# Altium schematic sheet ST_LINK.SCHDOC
size A4; Revision: B.2
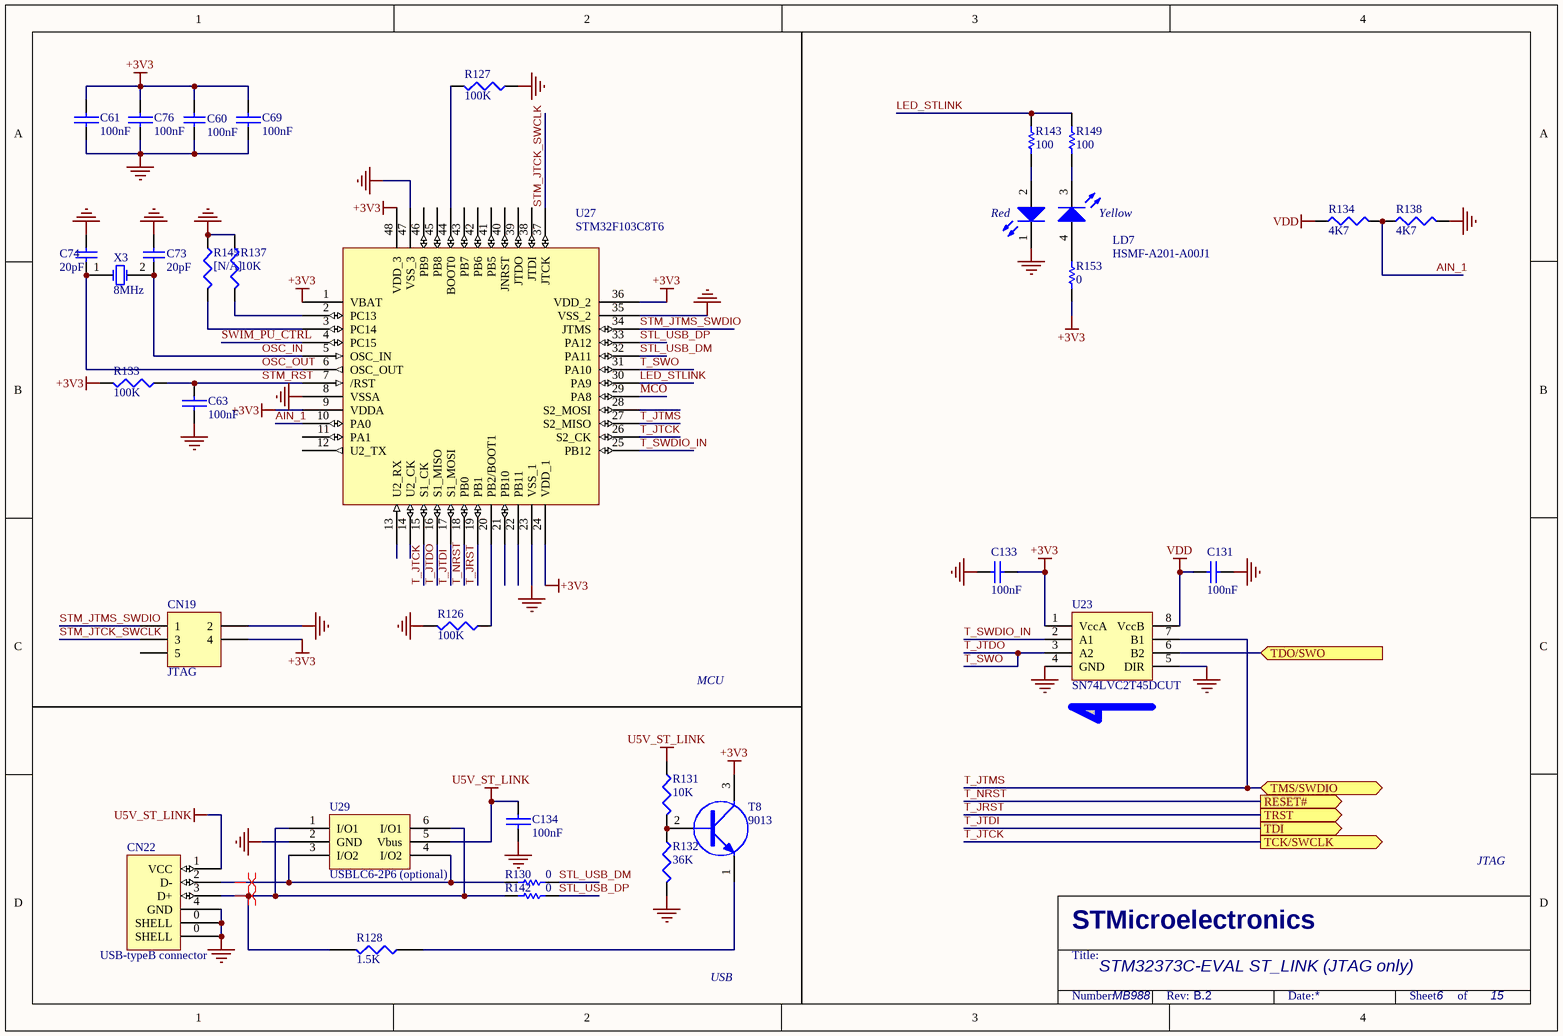
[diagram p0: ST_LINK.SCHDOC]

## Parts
C60  100nF  [0603C]
C61  100nF  [0603C]
C63  100nF  [0603C]
C69  100nF  [0603C]
C73  value 20pF  [0603R]  (hidden comment: Cap)
C74  value 20pF  [0603R]  (hidden comment: Cap)
C76  100nF  [0603C]
C131  100nF  [0603C]
C133  100nF  [0603C]
C134  100nF  [0603C]
CN19  JTAG  [2*3P]
CN22  USB-typeB connector  [USB-B]
LD7  HSMF-A201-A00J1  [LED2-28*32]
R126  100K  [0603R]
R127  100K  [0603R]
R128  1.5K  [0603R]
R130  0  [0603R]
R131  10K  [0603R]
R132  36K  [0603R]
R133  100K  [0603R]
R134  4K7  [0603R]
R137  10K  [0603R]
R138  4K7  [0603R]
R142  0  [0603R]
R143  100  [0603R]
R145  [N/A]  [0603R]
R149  100  [0603R]
R153  0  [0603R]
T8  9013  [SOT-23]
U23  SN74LVC2T45DCUT  [VSSOP8]
U27  STM32F103C8T6  [LQFP48]
U29  USBLC6-2P6 (optional)  [SOT-666]
X3  8MHz  [SMT_XTAL]

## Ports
RESET# (out), TCK/SWCLK (out), TDI (out), TDO/SWO (in), TMS/SWDIO (bidir), TRST (out)

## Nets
+3V3: C60.1 C61.2 C69.2 C76.2 C133.2 CN19.4 R133.2 R153.2 T8.3(C) U23.1(VccA) U27.1(VBAT) U27.9(VDDA) U27.24(VDD_1) U27.36(VDD_2) U27.48(VDD_3)
GND: C60.2 C61.1 C63.1 C69.1 C73.1 C74.1 C76.1 C131.2 C133.1 C134.2 CN19.2 CN22.0(SHELL) CN22.4(GND) LD7.1(RED_cathode) R126.2 R127.1 R132.2 R137.1 R138.2 R145.1 U23.4(GND) U23.5(DIR) U27.8(VSSA) U27.23(VSS_1) U27.35(VSS_2) U27.47(VSS_3) U29.2(GND)
U5V_ST_LINK: C134.1 CN22.1(VCC) R131.1 U29.5(Vbus)
VDD: C131.1 R134.1 U23.8(VccB)
AIN_1: R134.2 R138.1 U27.10(PA0)
LED_STLINK: R143.1 R149.1 U27.30(PA9)
MCO: U27.29(PA8)
OSC_IN: C73.2 U27.5(OSC_IN) X3.2(OSC2)
OSC_OUT: C74.2 U27.6(OSC_OUT) X3.1(OSC1)
STL_USB_DM: R130.1 U27.32(PA11)
STL_USB_DP: R142.1 U27.33(PA12)
STM_JTCK_SWCLK: CN19.3 U27.37(JTCK)
STM_JTMS_SWDIO: CN19.1 U27.34(JTMS)
STM_RST: C63.2 R133.1 U27.7(/RST)
SWIM_PU_CTRL: U27.4(PC15)
T_JRST: U27.19(PB1) ; port TRST
T_JTCK: U27.15(S1_CK) U27.26(S2_CK) ; port TCK/SWCLK
T_JTDI: U27.17(S1_MOSI) ; port TDI
T_JTDO: U23.3(A2) U27.16(S1_MISO) U27.31(PA10)  [also labelled T_SWO]
T_JTMS: U23.7(B1) U27.27(S2_MISO) ; port TMS/SWDIO
T_NRST: U27.18(PB0) ; port RESET#
T_SWDIO_IN: U23.2(A1) U27.25(PB12)
TDO/SWO: U23.6(B2) ; port TDO/SWO
NetCN22_2: CN22.2(D-) R130.2 U29.3(I/O2) U29.4(I/O2)
NetCN22_3: CN22.3(D+) R128.2 R142.2 U29.1(I/O1) U29.6(I/O1)
NetLD7_2: LD7.2(Red_anode) R143.2
NetLD7_3: LD7.3(YellowGreen_cathode) R149.2
NetLD7_4: LD7.4(YellowGreen_anode) R153.1
NetR126_1: R126.1 U27.20(PB2/BOOT1)
NetR127_2: R127.2 U27.44(BOOT0)
NetR128_1: R128.1 T8.1(E)
NetR131_2: R131.2 R132.1 T8.2(B)
NetR137_2: R137.2 U27.2(PC13)
NetR145_2: R145.2 U27.3(PC14)

Not connected (* = marked no-connect by the designer): CN19 5; U27 11(PA1) 12(U2_TX) 13(U2_RX) 14(U2_CK) 21(PB10) 22(PB11) 28(S2_MOSI) 38(JTDI) 39(JTDO) 40(JNRST) 41(PB5) 42(PB6) 43(PB7) 45(PB8) 46(PB9)

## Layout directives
differential pair: NetCN22_2, NetCN22_3

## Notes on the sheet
- MCU
- JTAG
- USB
- STM32373C-EVAL ST_LINK (JTAG only)
- MB988
- 6
- 15

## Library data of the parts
C60 = Cap: Capacitor; Value: 10nF
C61 C63 C69 C76 = CAP
C73 C74 = Cap: Capacitor
C131 C133 = CAP: Capacitor; Value: 100pF
C134 = CAP: Capacitor
CN19 = Header 3X2: Header, 3-Pin, Dual row
R126-R128 R133 R134 R138 = RES1
R130 R142 R143 R149 R153 = Res1: Resistor; Value: 1K
R131 R132 R137 R145 = R: Right: 20; Bottom: 30
T8 = NPN
U27 = STM32F10x(48pin)
U29 = USBLC6-2
X3 = XTAL: Crystal Oscillator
